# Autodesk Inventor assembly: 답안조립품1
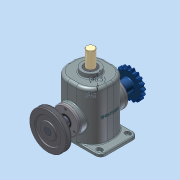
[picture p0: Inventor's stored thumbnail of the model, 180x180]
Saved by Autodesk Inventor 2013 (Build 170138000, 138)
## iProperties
Created: 2014-12
Part Number: 답안조립품1
Document SubType Name: Assembly
Designer: user
Mass: 8252.46 g
Surface Area: 4222.84 cm^2
Volume: 1869.06 cm^3
Density: 4.41531 g/cm^3
Author: user
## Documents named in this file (15)
- C:\Documents and Settings\user\바탕 화면\341208V1001\답안조립품1.iam
- C:\Documents and Settings\user\바탕 화면\341208V1001\본체.ipt
- C:\Documents and Settings\user\바탕 화면\341208V1001\편심축.ipt
- C:\Documents and Settings\user\바탕 화면\341208V1001\V-벨트풀리.ipt
- C:\Documents and Settings\user\바탕 화면\341208V1001\체인 스프로킷.ipt
- C:\Documents and Settings\user\바탕 화면\341208V1001\커버.ipt
- C:\Documents and Settings\user\바탕 화면\341208V1001\슬라이드.ipt
- C:\Documents and Settings\user\바탕 화면\341208V1001\가변스프링.ipt
- C:\Documents and Settings\user\바탕 화면\341208V1001\베어링 6205.ipt
- C:\Documents and Settings\user\바탕 화면\341208V1001\오일실.ipt
- C:\Documents and Settings\user\바탕 화면\341208V1001\부시.ipt
- C:\Documents and Settings\user\바탕 화면\341208V1001\키 8x8.ipt
- C:\Documents and Settings\user\바탕 화면\341208V1001\멈춤링.ipt
- C:\Documents and Settings\user\바탕 화면\341208V1001\M4x0.5.ipt
- C:\Documents and Settings\user\바탕 화면\341208V1001\멈춤나사 M5x0.5.ipt
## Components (9 placed, 4 different names)
1. V-벨트풀리:1
2. 5-체인 스프로킷:1
3. 가변스프링:1
4. M4x0.5:1
5. M4x0.5:2
6. M4x0.5:3
7. M4x0.5:4
8. M4x0.5:5
9. M4x0.5:6
